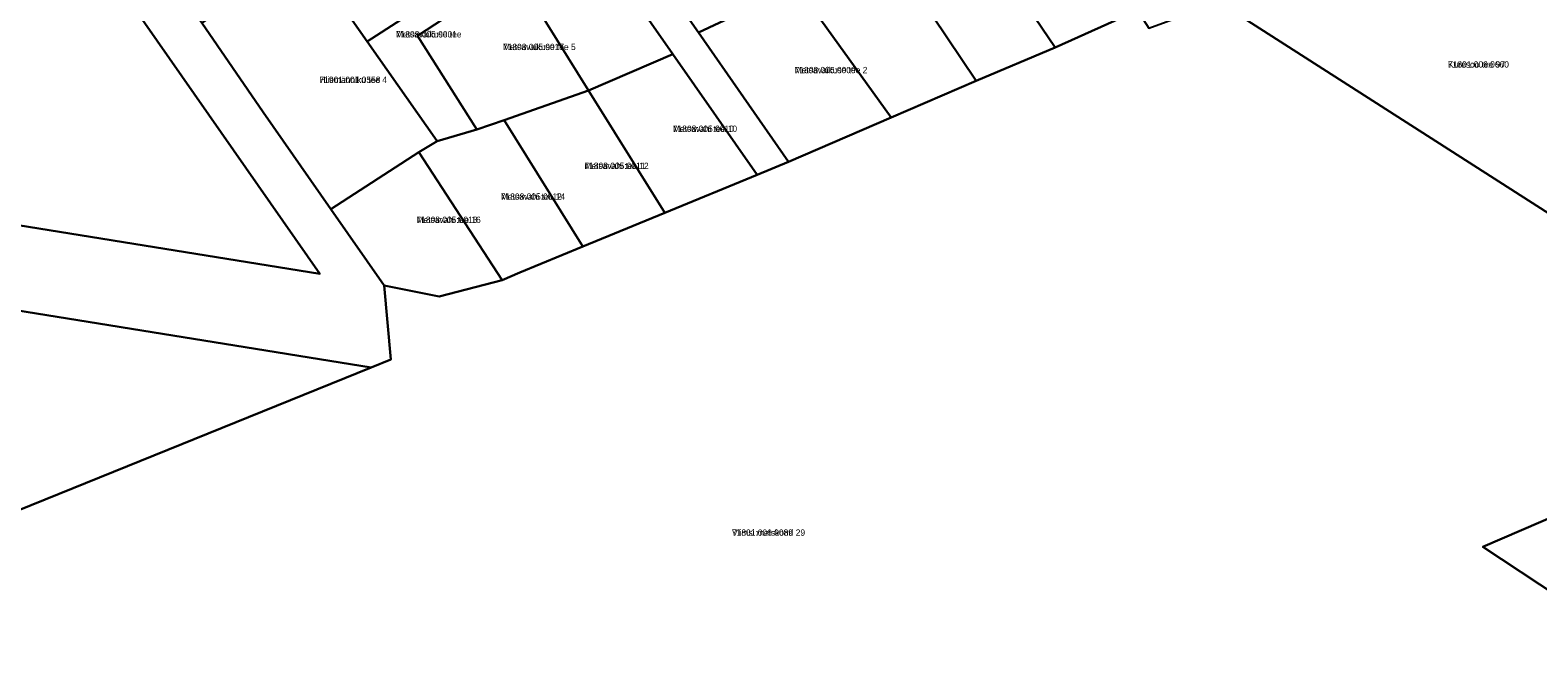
# Model space of a CAD drawing. Extents: x 529768 to 552006, y 6562269 to 6580975.
# Drawn here: x 536881.3 to 537239.9, y 6569221.9 to 6569374.1 of the extents above; entities that cross this region are included whole.
import ezdxf

# ---------------------------------------------------------------- set-up
doc = ezdxf.new("R2010")
doc.units = 0
for name, color, linetype in [('L_AADRESS', 7, 'Continuous'), ('PIIR', 7, 'Continuous'), ('TUNNUS', 7, 'Continuous')]:
    doc.layers.add(name, color=color, linetype=linetype)

msp = doc.modelspace()

# ---------------------------------------------------------------- linework, layer by layer
at = {"layer": 'PIIR'}
for points in [[(536660.44, 6569597.72), (536680.38, 6569359.64), (536681.71, 6569343.63), (536686.07, 6569338.44), (536784.68, 6569221.92), (536962.4, 6569293.88), (536967.09, 6569295.8), (536965.47, 6569313.36), (536978.54, 6569310.73), (536993.55, 6569314.63), (536997.71, 6569316.46), (537012.75, 6569322.66), (537032.22, 6569330.68), (537054.2, 6569339.74), (537061.66, 6569342.81), (537086.06, 6569353.34), (537106.33, 6569362.09), (537125.11, 6569370.01), (537144.7, 6569378.86), (537147.4, 6569374.65), (537163.87, 6569380.63), (537170.73, 6569376.5), (537249.6, 6569325.97)], [(537282.55, 6569275.19), (537226.88, 6569251.23), (537262.82, 6569227.37)]]:
    msp.add_lwpolyline(points, dxfattribs=at)
for points in [[(536859.68, 6569503.73), (536921.53, 6569535.04), (536945.91, 6569500.32), (536965.43, 6569472.6), (536931.92, 6569455.78), (536903.85, 6569441.56), (536883.15, 6569431.43), (536903.1, 6569402.6), (536893.87, 6569396.93), (536950.16, 6569316.12), (536851.28, 6569332.09), (536848.04, 6569336.59), (536846.9, 6569338.28), (536801.14, 6569403.41), (536764.48, 6569455.44), (536767.12, 6569456.78)], [(537114.67, 6569421.13), (537144.7, 6569378.86), (537125.11, 6569370.01), (537098.41, 6569409.48)], [(537019.36, 6569403.4), (537040.96, 6569418.86), (537063.67, 6569384.61), (537040.22, 6569373.55)], [(537098.41, 6569409.48), (537125.11, 6569370.01), (537106.33, 6569362.09), (537082.1, 6569398.14)], [(536947.03, 6569392.09), (536971.94, 6569408.06), (536986.53, 6569387.68), (536961.46, 6569371.46)], [(536893.87, 6569396.93), (536903.1, 6569402.6), (536906.64, 6569397.48), (536922.06, 6569375.91), (536936.68, 6569354.64), (536952.79, 6569331.58), (536965.47, 6569313.36), (536967.09, 6569295.8), (536962.4, 6569293.88), (536686.07, 6569338.44), (536681.71, 6569343.63), (536680.38, 6569359.64), (536851.28, 6569332.09), (536950.16, 6569316.12)], [(536986.53, 6569387.68), (537010.62, 6569403.35), (537011.63, 6569404.01), (537013.27, 6569405.08), (537013.91, 6569404.18), (537019.36, 6569403.4), (537040.22, 6569373.55), (537061.66, 6569342.81), (537054.2, 6569339.74), (537034.18, 6569368.42), (537012.97, 6569398.8), (536996.54, 6569388), (536973.39, 6569372.77), (536987.52, 6569350.54), (536978.11, 6569347.76), (536961.46, 6569371.46)], [(537251.88, 6569357.54), (537249.6, 6569325.97), (537170.73, 6569376.5), (537203.24, 6569392.77), (537233.07, 6569404.52)], [(537012.97, 6569398.8), (537034.18, 6569368.42), (537014.11, 6569359.78), (536996.54, 6569388)], [(537082.1, 6569398.14), (537106.33, 6569362.09), (537086.06, 6569353.34), (537063.67, 6569384.61)], [(536936.68, 6569354.64), (536922.06, 6569375.91), (536947.03, 6569392.09), (536961.46, 6569371.46), (536978.11, 6569347.76), (536973.7, 6569345.09), (536952.79, 6569331.58)], [(536973.39, 6569372.77), (536996.54, 6569388), (537014.11, 6569359.78), (536994.03, 6569352.73), (536987.52, 6569350.54)], [(537040.22, 6569373.55), (537063.67, 6569384.61), (537086.06, 6569353.34), (537061.66, 6569342.81)], [(537014.11, 6569359.78), (537034.18, 6569368.42), (537054.2, 6569339.74), (537032.22, 6569330.68)], [(536994.03, 6569352.73), (537014.11, 6569359.78), (537032.22, 6569330.68), (537012.75, 6569322.66)], [(536978.11, 6569347.76), (536987.52, 6569350.54), (536994.03, 6569352.73), (537012.75, 6569322.66), (536997.71, 6569316.46), (536993.55, 6569314.63), (536973.7, 6569345.09)], [(536952.79, 6569331.58), (536973.7, 6569345.09), (536993.55, 6569314.63), (536978.54, 6569310.73), (536965.47, 6569313.36)], [(536784.68, 6569221.92), (536686.07, 6569338.44), (536962.4, 6569293.88)], [(537282.55, 6569275.19), (537291.25, 6569269.49), (537287.93, 6569264.5), (537262.82, 6569227.37), (537226.88, 6569251.23)]]:
    msp.add_lwpolyline(points, close=True, dxfattribs=at)

# ---------------------------------------------------------------- texts
at = {"layer": 'L_AADRESS'}
for s, p in [('Metsavaikuse tee', (536968.27, 6569372.41)), ('Metsavaikuse tee 5', (536993.75, 6569369.4)), ('Kuresoo tee 97', (537218.55, 6569365.24)), ('Hiiemänniku tee 4', (536950.09, 6569361.59)), ('Metsavaikuse tee 2', (537063.14, 6569363.9)), ('Metsavahi tee 10', (537034.16, 6569349.94)), ('Metsavahi tee 12', (537013.12, 6569341.12)), ('Metsavahi tee 14', (536993.23, 6569333.79)), ('Metsavahi tee 16', (536973.17, 6569328.28)), ('Viimsi metskond 29', (537048.22, 6569253.83))]:
    msp.add_text(s, height=1.5, dxfattribs=at).set_placement(p)
at = {"layer": 'TUNNUS'}
for s, p in [('71808:005:0001', (536968.27, 6569372.41)), ('71808:005:0017', (536993.75, 6569369.4)), ('71801:006:0660', (537218.55, 6569365.24)), ('71901:001:0558', (536950.09, 6569361.59)), ('71808:005:0009', (537063.14, 6569363.9)), ('71808:005:0010', (537034.16, 6569349.94)), ('71808:005:0011', (537013.12, 6569341.12)), ('71808:005:0012', (536993.23, 6569333.79)), ('71808:005:0013', (536973.17, 6569328.28)), ('71801:006:0089', (537048.22, 6569253.83))]:
    msp.add_text(s, height=1.5, dxfattribs=at).set_placement(p)

doc.saveas('drawing.dxf')
